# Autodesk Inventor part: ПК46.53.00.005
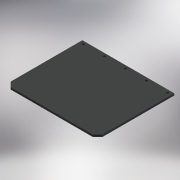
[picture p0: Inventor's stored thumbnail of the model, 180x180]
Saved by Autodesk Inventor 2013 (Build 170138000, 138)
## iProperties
Created: 2005-03
Part Number: ПК46.53.00.005
Material: Silicone
Document SubType Name: Modeling
Designer: HKostja
Manufacturer: Standard
Standards Organization: Custom
Description: Брызговик
Density: 1.25 g/cm^3
Mass: 2385.12 g
Surface Area: 4008.11 cm^2
Volume: 1908.1 cm^3
Author: HKostja
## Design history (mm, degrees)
sketch "Эскиз1" dims "d14" = 10
  geometry: L1 (0, 0)-(-480, 0); L2 (-480, 0)-(-480, -375); L3 (-455, -400)-(-25, -400); L4 (0, -375)-(0, 0); L5 (-480, -375)-(-455, -400); L6 (-25, -400)-(0, -375); C1 r 6 at (-460, -15); C2 r 6 at (-350, -15); C3 r 6 at (-240, -15); C4 r 6 at (-130, -15); C5 r 6 at (-20, -15); 2 further points
  constraints: 12 end point, 5 centre point, 4 point on line, 2 horizontal, 2 parallel, 1 perpendicular, 9 other
  dimensions: "d0" = 400 distance between parallel lines of L1 L3; "d1" = 480 distance between parallel lines of L2 L4; "d2" = 25 distance of L2.end point (-480, -400); "d3" = 25 distance of L3.start point (-480, -400) (= d2); "d4" = 25 distance of L3.end point (0, -400) (= d2); "d5" = 25 distance of L4.start point (0, -400) (= d4); "d6" = 12 diameter of C1; "d7" = 15 distance from line of L1 C1.centre; "d8" = 20 distance from line of L2 C1.centre; "d11" = 110 distance of C1.centre C2.centre
extrude "Выдавливание1" new body sketch "Эскиз1" distance "d16" = 10; taper "d17" = 0 deg
body "Solid1"
